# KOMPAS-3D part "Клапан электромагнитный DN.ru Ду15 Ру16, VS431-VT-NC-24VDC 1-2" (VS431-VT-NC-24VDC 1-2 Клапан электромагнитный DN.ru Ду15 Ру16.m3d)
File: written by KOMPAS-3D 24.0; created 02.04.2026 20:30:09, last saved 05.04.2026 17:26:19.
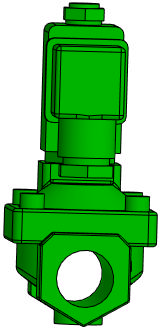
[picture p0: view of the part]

Document properties: Автор: artio; Полное имя файла: C:\Users\artio\OneDrive\Рабочий стол\Клапан электромагнитный DN.ru\VS431\VS431-VT-NC\VS431-VT-NC-24VDC\Ду15\VS431-VT-NC-24VDC 1-2 Клапан электромагнитный DN.ru Ду15 Ру16.m3d

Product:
- Body: Тело 1  | qty 1
    Масса: 1.030062
- Part/product: Клапан электромагнитный DN.ru Ду15 Ру16  | designation VS431-VT-NC-24VDC 1-2
    Масса: 0.732
    Раздел спецификации: Прочие изделия
    Примечание: D130-04754
    additional columns: ef56311e-7521-43dc-8291-0e6108b3d81d; VS400-ET-NC-220VAC 1-2; artio; c; Шероховатость не задана; Да

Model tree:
1. Операция без истории:1

Expressions: VS431-VT-NC-24VDC 1-2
